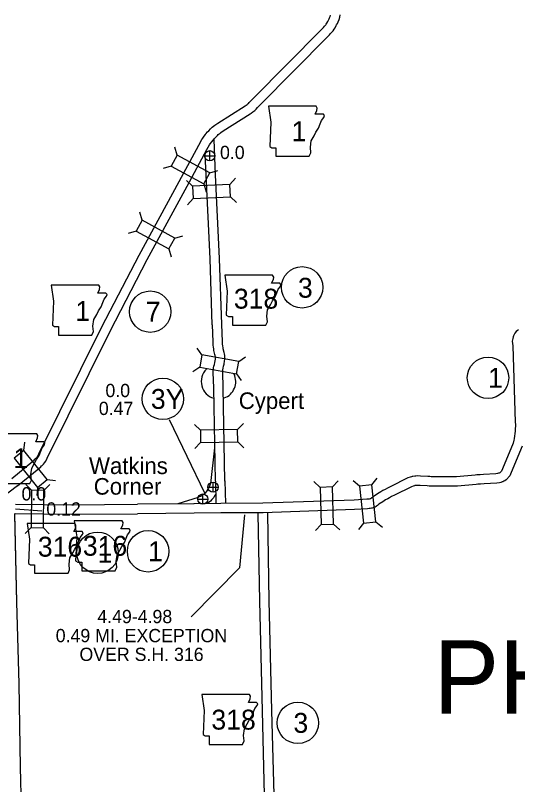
# Model space of a CAD drawing. Extents: x -939622 to -934222, y 1383701 to 1385301.
# Drawn here: x -935874.6 to -935826.6, y 1383989.8 to 1384063.3 of the extents above; entities that cross this region are included whole.
import ezdxf

# ---------------------------------------------------------------- set-up
doc = ezdxf.new("R2010")
doc.units = 0
for name, color, linetype in [('Default', 7, 'Continuous'), ('Level 10', 7, 'Continuous'), ('Level 2', 7, 'Continuous'), ('Level 20', 7, 'Continuous'), ('Level 21', 7, 'Continuous'), ('Level 24', 7, 'Continuous'), ('Level 25', 7, 'Continuous'), ('Level 26', 7, 'Continuous'), ('Level 27', 7, 'Continuous')]:
    doc.layers.add(name, color=color, linetype=linetype)

msp = doc.modelspace()

# ---------------------------------------------------------------- linework, layer by layer
at = {"layer": 'Level 10'}
for points in [[(-935856.422, 1384051.991), (-935856.278, 1384052.175), (-935856.151, 1384052.289), (-935855.982, 1384052.472), (-935855.832, 1384052.628), (-935855.694, 1384052.726), (-935855.568, 1384052.827), (-935855.48, 1384052.876), (-935855.279, 1384053.028), (-935852.676, 1384054.679), (-935852.582, 1384054.738), (-935852.473, 1384054.816), (-935852.405, 1384054.867), (-935852.357, 1384054.907), (-935852.282, 1384054.981), (-935852.149, 1384055.124), (-935851.897, 1384055.38), (-935845.4, 1384061.952), (-935845.239, 1384062.101), (-935845.179, 1384062.169), (-935845.086, 1384062.275), (-935845.015, 1384062.359), (-935844.956, 1384062.419), (-935844.918, 1384062.475), (-935844.865, 1384062.562), (-935844.775, 1384062.745), (-935844.715, 1384062.86), (-935844.644, 1384062.984), (-935844.597, 1384063.07), (-935844.553, 1384063.197), (-935844.512, 1384063.327)], [(-935855.713, 1384051.437), (-935855.618, 1384051.559), (-935855.519, 1384051.648), (-935855.328, 1384051.854), (-935855.242, 1384051.943), (-935855.153, 1384052.006), (-935855.064, 1384052.077), (-935854.988, 1384052.12), (-935854.766, 1384052.287), (-935852.199, 1384053.916), (-935852.083, 1384053.988), (-935851.941, 1384054.09), (-935851.847, 1384054.16), (-935851.75, 1384054.241), (-935851.635, 1384054.355), (-935851.499, 1384054.502), (-935851.256, 1384054.749), (-935844.773, 1384061.305), (-935844.594, 1384061.473), (-935844.505, 1384061.574), (-935844.404, 1384061.687), (-935844.349, 1384061.753), (-935844.259, 1384061.844), (-935844.162, 1384061.987), (-935844.075, 1384062.129), (-935843.971, 1384062.34), (-935843.926, 1384062.428), (-935843.858, 1384062.545), (-935843.771, 1384062.706), (-935843.698, 1384062.915), (-935843.628, 1384063.14), (-935843.603, 1384063.357)], [(-935866.365, 1384033.548), (-935862.82, 1384040.409), (-935858.995, 1384047.442), (-935857.116, 1384050.921), (-935856.822, 1384051.463), (-935856.709, 1384051.599), (-935856.582, 1384051.767), (-935856.464, 1384051.937), (-935856.422, 1384051.991)], [(-935865.565, 1384033.135), (-935862.025, 1384039.988), (-935858.204, 1384047.013), (-935856.324, 1384050.493), (-935856.073, 1384050.956), (-935856.004, 1384051.039), (-935855.852, 1384051.239), (-935855.739, 1384051.404), (-935855.713, 1384051.437)], [(-935854.911, 1384033.791), (-935855.127, 1384040.095), (-935855.513, 1384048.097), (-935855.643, 1384051.458)], [(-935855.811, 1384033.76), (-935856.027, 1384040.058), (-935856.412, 1384048.058), (-935856.489, 1384050.045)], [(-935874.994, 1384019.077), (-935872.977, 1384020.714), (-935872.851, 1384020.82), (-935872.77, 1384020.913), (-935872.678, 1384020.993), (-935872.621, 1384021.045), (-935872.577, 1384021.102), (-935872.497, 1384021.21), (-935872.386, 1384021.42), (-935866.368, 1384033.542)], [(-935874.427, 1384018.378), (-935872.402, 1384020.021), (-935872.219, 1384020.177), (-935872.135, 1384020.273), (-935872.078, 1384020.321), (-935871.956, 1384020.434), (-935871.86, 1384020.558), (-935871.733, 1384020.73), (-935871.585, 1384021.01), (-935865.562, 1384033.141)], [(-935826.538, 1384033.284), (-935826.624, 1384033.222), (-935826.775, 1384033.104), (-935826.889, 1384032.955), (-935826.956, 1384032.823), (-935827.007, 1384032.702), (-935827.035, 1384032.588), (-935827.082, 1384032.437), (-935827.141, 1384032.202), (-935827.094, 1384031.727), (-935826.855, 1384024.434), (-935826.83, 1384024.216), (-935826.835, 1384024.09), (-935826.853, 1384023.798), (-935826.851, 1384023.623), (-935826.886, 1384023.324), (-935826.908, 1384023.154), (-935826.965, 1384022.856), (-935826.991, 1384022.717), (-935827.058, 1384022.43), (-935828.08, 1384019.982), (-935828.173, 1384019.764), (-935828.174, 1384019.763), (-935828.191, 1384019.742), (-935828.228, 1384019.703), (-935828.273, 1384019.655), (-935828.299, 1384019.628), (-935828.305, 1384019.624), (-935828.321, 1384019.616), (-935828.388, 1384019.588), (-935828.413, 1384019.577), (-935828.461, 1384019.561), (-935828.538, 1384019.543), (-935828.718, 1384019.509), (-935829.877, 1384019.451), (-935830.218, 1384019.426), (-935830.394, 1384019.415), (-935830.508, 1384019.41), (-935830.689, 1384019.389), (-935832.454, 1384019.236), (-935832.554, 1384019.225), (-935832.688, 1384019.223), (-935832.814, 1384019.224), (-935833.535, 1384019.225), (-935833.913, 1384019.224), (-935834.144, 1384019.23), (-935834.491, 1384019.223), (-935834.888, 1384019.236), (-935835.031, 1384019.24), (-935835.204, 1384019.249), (-935835.898, 1384019.299), (-935836.154, 1384019.306), (-935836.344, 1384019.303), (-935836.466, 1384019.298), (-935836.629, 1384019.271), (-935836.71, 1384019.249), (-935836.768, 1384019.23), (-935836.9, 1384019.189), (-935837.115, 1384019.115), (-935838.805, 1384018.275), (-935839.075, 1384018.137), (-935839.301, 1384018.027), (-935839.502, 1384017.91), (-935839.712, 1384017.784), (-935840.011, 1384017.601), (-935840.421, 1384017.327), (-935840.584, 1384017.2), (-935840.679, 1384017.122), (-935840.689, 1384017.119), (-935840.718, 1384017.116), (-935840.823, 1384017.1), (-935840.923, 1384017.091), (-935841.039, 1384017.078), (-935842.266, 1384016.998), (-935850.983, 1384016.698), (-935855.007, 1384016.669), (-935857.564, 1384016.639)], [(-935855.515, 1384018.81), (-935855.659, 1384027.735), (-935855.719, 1384029.18), (-935855.718, 1384029.38), (-935855.71, 1384029.517), (-935855.683, 1384029.635), (-935855.652, 1384029.793), (-935855.61, 1384029.973), (-935855.579, 1384030.148), (-935855.523, 1384030.456), (-935855.513, 1384030.525), (-935855.509, 1384030.572), (-935855.513, 1384030.617), (-935855.52, 1384030.677), (-935855.544, 1384030.81), (-935855.563, 1384030.914), (-935855.661, 1384031.302), (-935855.669, 1384031.425), (-935855.703, 1384031.638), (-935855.719, 1384031.763), (-935855.731, 1384031.949), (-935855.739, 1384032.113), (-935855.81, 1384033.756)], [(-935854.615, 1384018.825), (-935854.76, 1384027.761), (-935854.819, 1384029.197), (-935854.818, 1384029.352), (-935854.816, 1384029.39), (-935854.803, 1384029.447), (-935854.772, 1384029.603), (-935854.729, 1384029.791), (-935854.693, 1384029.989), (-935854.636, 1384030.308), (-935854.618, 1384030.421), (-935854.606, 1384030.572), (-935854.617, 1384030.707), (-935854.63, 1384030.81), (-935854.658, 1384030.971), (-935854.683, 1384031.107), (-935854.769, 1384031.445), (-935854.774, 1384031.527), (-935854.812, 1384031.764), (-935854.823, 1384031.849), (-935854.833, 1384032), (-935854.84, 1384032.155), (-935854.911, 1384033.795)], [(-935826.198, 1384022.153), (-935827.251, 1384019.632), (-935827.38, 1384019.329), (-935827.45, 1384019.227), (-935827.516, 1384019.145), (-935827.573, 1384019.086), (-935827.618, 1384019.037), (-935827.71, 1384018.943), (-935827.841, 1384018.849), (-935827.95, 1384018.795), (-935828.033, 1384018.761), (-935828.091, 1384018.735), (-935828.216, 1384018.694), (-935828.349, 1384018.662), (-935828.612, 1384018.613), (-935829.822, 1384018.553), (-935830.158, 1384018.528), (-935830.348, 1384018.516), (-935830.437, 1384018.513), (-935830.598, 1384018.494), (-935832.364, 1384018.34), (-935832.497, 1384018.325), (-935832.688, 1384018.323), (-935832.82, 1384018.324), (-935833.533, 1384018.325), (-935833.923, 1384018.324), (-935834.148, 1384018.33), (-935834.497, 1384018.323), (-935834.916, 1384018.336), (-935835.068, 1384018.341), (-935835.261, 1384018.351), (-935835.942, 1384018.4), (-935836.16, 1384018.406), (-935836.318, 1384018.404), (-935836.371, 1384018.401), (-935836.441, 1384018.39), (-935836.456, 1384018.386), (-935836.493, 1384018.373), (-935836.618, 1384018.334), (-935836.768, 1384018.283), (-935838.4, 1384017.471), (-935838.673, 1384017.332), (-935838.876, 1384017.233), (-935839.045, 1384017.135), (-935839.245, 1384017.015), (-935839.525, 1384016.843), (-935839.894, 1384016.596), (-935840.022, 1384016.497), (-935840.11, 1384016.425), (-935840.139, 1384016.401), (-935840.233, 1384016.316), (-935840.533, 1384016.232), (-935840.598, 1384016.224), (-935840.715, 1384016.206), (-935840.831, 1384016.195), (-935840.96, 1384016.181), (-935842.221, 1384016.099), (-935850.965, 1384015.798), (-935854.999, 1384015.769), (-935857.554, 1384015.739)], [(-935855.599, 1384021.999), (-935855.997, 1384018.598), (-935856.007, 1384018.509), (-935856.012, 1384018.49), (-935856.05, 1384018.413), (-935856.138, 1384018.22), (-935856.179, 1384018.146), (-935856.247, 1384018.031), (-935856.343, 1384017.883), (-935856.411, 1384017.778), (-935856.437, 1384017.746), (-935856.504, 1384017.673), (-935856.603, 1384017.574), (-935856.664, 1384017.522), (-935856.735, 1384017.47), (-935856.819, 1384017.424), (-935856.942, 1384017.357), (-935857.058, 1384017.299), (-935857.126, 1384017.269), (-935857.176, 1384017.253), (-935859.104, 1384016.645)], [(-935855.515, 1384018.807), (-935855.464, 1384016.672)], [(-935854.615, 1384018.828), (-935854.564, 1384016.672)], [(-935874.443, 1384018.366), (-935876.198, 1384017.071), (-935878.006, 1384015.744), (-935878.186, 1384015.587)], [(-935855.505, 1384017.521), (-935855.587, 1384017.394), (-935855.682, 1384017.249), (-935855.756, 1384017.157), (-935855.853, 1384017.051), (-935855.993, 1384016.911), (-935856.108, 1384016.813), (-935856.251, 1384016.709), (-935856.34, 1384016.661)], [(-935874.639, 1384016.626), (-935869.261, 1384016.558), (-935862.965, 1384016.596)], [(-935857.562, 1384016.639), (-935862.966, 1384016.596)], [(-935874.651, 1384015.727), (-935869.264, 1384015.658), (-935862.959, 1384015.696)], [(-935857.555, 1384015.739), (-935862.959, 1384015.696)], [(-935850.814, 1383988.81), (-935851.014, 1383996.866), (-935851.268, 1384007.347), (-935851.415, 1384015.729)], [(-935849.914, 1383988.822), (-935850.114, 1383996.888), (-935850.368, 1384007.366), (-935850.515, 1384015.757)]]:
    msp.add_lwpolyline(points, dxfattribs=at)
at = {"layer": 'Level 2'}
for points in [[(-935874.733, 1384015.72), (-935874.523, 1384007.256), (-935874.318, 1383999.431), (-935874.179, 1383991.495), (-935873.992, 1383983.582), (-935873.79, 1383975.609), (-935873.634, 1383967.743), (-935873.76, 1383967.737), (-935873.69, 1383964.539)], [(-935874.73, 1384015.616), (-935874.523, 1384007.256), (-935874.318, 1383999.431), (-935874.179, 1383991.495), (-935873.992, 1383983.582), (-935873.79, 1383975.609), (-935873.634, 1383967.743), (-935873.76, 1383967.737), (-935873.69, 1383964.539)]]:
    msp.add_lwpolyline(points, dxfattribs=at)
at = {"layer": 'Level 20'}
for p, q in [((-935859.185, 1384049.951), (-935859.411, 1384050.71)), ((-935859.749, 1384048.906), (-935860.508, 1384048.68)), ((-935856.049, 1384048.257), (-935855.29, 1384048.484)), ((-935857.694, 1384047.002), (-935858.279, 1384047.535)), ((-935856.614, 1384047.212), (-935856.387, 1384046.453)), ((-935854.133, 1384047.166), (-935853.6, 1384047.752)), ((-935857.639, 1384045.815), (-935858.172, 1384045.23)), ((-935854.079, 1384045.98), (-935853.493, 1384045.446)), ((-935862.517, 1384043.752), (-935862.739, 1384044.512)), ((-935863.086, 1384042.71), (-935863.846, 1384042.487)), ((-935859.389, 1384042.043), (-935858.629, 1384042.266)), ((-935859.959, 1384041.001), (-935859.736, 1384040.241)), ((-935856.8, 1384030.883), (-935857.251, 1384031.534)), ((-935853.292, 1384030.25), (-935852.642, 1384030.702)), ((-935857.011, 1384029.714), (-935857.661, 1384029.262)), ((-935853.503, 1384029.081), (-935853.051, 1384028.431)), ((-935853.39, 1384023.747), (-935852.839, 1384024.316)), ((-935856.953, 1384023.69), (-935857.523, 1384024.24)), ((-935853.39, 1384023.747), (-935856.953, 1384023.69)), ((-935856.953, 1384023.69), (-935856.934, 1384022.502)), ((-935853.371, 1384022.559), (-935853.39, 1384023.747)), ((-935873.826, 1384021.738), (-935873.743, 1384022.526)), ((-935856.934, 1384022.502), (-935857.485, 1384021.933)), ((-935856.934, 1384022.502), (-935853.371, 1384022.559)), ((-935853.371, 1384022.559), (-935852.802, 1384022.009)), ((-935873.092, 1384017.939), (-935873.645, 1384018.506)), ((-935871.904, 1384017.924), (-935871.337, 1384018.477)), ((-935871.586, 1384018.966), (-935870.799, 1384018.883)), ((-935845.516, 1384018.22), (-935846.094, 1384018.762)), ((-935844.329, 1384018.259), (-935843.787, 1384018.837)), ((-935841.732, 1384018.343), (-935842.349, 1384018.84)), ((-935840.551, 1384018.47), (-935840.054, 1384019.087)), ((-935872.51, 1384018.22), (-935872.594, 1384017.432)), ((-935841.351, 1384014.8), (-935841.848, 1384014.183)), ((-935840.17, 1384014.927), (-935839.553, 1384014.43)), ((-935873.137, 1384014.375), (-935873.704, 1384013.822)), ((-935871.949, 1384014.36), (-935871.396, 1384013.793)), ((-935845.4, 1384014.658), (-935845.942, 1384014.08)), ((-935844.213, 1384014.697), (-935843.635, 1384014.155))]:
    msp.add_line(p, q, dxfattribs=at)
for points in [[(-935859.749, 1384048.906), (-935856.614, 1384047.212), (-935856.049, 1384048.257), (-935859.185, 1384049.951)], [(-935857.639, 1384045.815), (-935854.079, 1384045.98), (-935854.133, 1384047.166), (-935857.694, 1384047.002)], [(-935859.389, 1384042.043), (-935862.517, 1384043.752), (-935863.086, 1384042.71), (-935859.959, 1384041.001)], [(-935857.011, 1384029.714), (-935853.503, 1384029.081), (-935853.292, 1384030.25), (-935856.8, 1384030.883)], [(-935874.75, 1384020.992), (-935872.51, 1384018.22), (-935871.586, 1384018.966), (-935873.826, 1384021.738)], [(-935840.17, 1384014.927), (-935840.551, 1384018.47), (-935841.732, 1384018.343), (-935841.351, 1384014.8)], [(-935871.949, 1384014.36), (-935871.904, 1384017.924), (-935873.092, 1384017.939), (-935873.137, 1384014.375)], [(-935845.516, 1384018.22), (-935845.4, 1384014.658), (-935844.213, 1384014.697), (-935844.329, 1384018.259)]]:
    msp.add_lwpolyline(points, close=True, dxfattribs=at)
at = {"layer": 'Level 21'}
for points in [[(-935850.449, 1384054.63), (-935850.22, 1384053.107), (-935850.322, 1384050.798), (-935850.119, 1384050.671), (-935849.738, 1384050.671), (-935849.738, 1384049.859), (-935846.541, 1384049.859), (-935846.388, 1384050.189), (-935846.439, 1384050.722), (-935846.363, 1384051.331), (-935846.084, 1384051.813), (-935845.906, 1384052.168), (-935845.652, 1384052.549), (-935845.5, 1384052.955), (-935845.373, 1384053.285), (-935845.145, 1384053.564), (-935845.094, 1384053.741), (-935845.196, 1384053.868), (-935845.982, 1384053.868), (-935845.805, 1384054.224), (-935845.779, 1384054.452), (-935845.885, 1384054.627)], [(-935854.606, 1384038.491), (-935854.377, 1384036.968), (-935854.479, 1384034.659), (-935854.276, 1384034.532), (-935853.895, 1384034.532), (-935853.895, 1384033.72), (-935850.698, 1384033.72), (-935850.546, 1384034.05), (-935850.596, 1384034.583), (-935850.52, 1384035.192), (-935850.241, 1384035.674), (-935850.063, 1384036.029), (-935849.81, 1384036.41), (-935849.657, 1384036.816), (-935849.53, 1384037.146), (-935849.302, 1384037.425), (-935849.251, 1384037.603), (-935849.353, 1384037.73), (-935850.14, 1384037.73), (-935849.962, 1384038.085), (-935849.937, 1384038.313), (-935850.042, 1384038.489)], [(-935871.231, 1384037.542), (-935871.002, 1384036.019), (-935871.104, 1384033.71), (-935870.901, 1384033.583), (-935870.52, 1384033.583), (-935870.52, 1384032.771), (-935867.323, 1384032.771), (-935867.17, 1384033.101), (-935867.221, 1384033.634), (-935867.145, 1384034.243), (-935866.866, 1384034.725), (-935866.688, 1384035.08), (-935866.435, 1384035.461), (-935866.282, 1384035.867), (-935866.155, 1384036.197), (-935865.927, 1384036.476), (-935865.876, 1384036.654), (-935865.978, 1384036.781), (-935866.764, 1384036.781), (-935866.587, 1384037.136), (-935866.561, 1384037.364), (-935866.667, 1384037.54)], [(-935877.164, 1384023.345), (-935876.935, 1384021.823), (-935877.037, 1384019.513), (-935876.834, 1384019.386), (-935876.453, 1384019.386), (-935876.453, 1384018.574), (-935873.256, 1384018.574), (-935873.104, 1384018.904), (-935873.154, 1384019.437), (-935873.078, 1384020.046), (-935872.799, 1384020.528), (-935872.621, 1384020.884), (-935872.368, 1384021.264), (-935872.215, 1384021.67), (-935872.088, 1384022), (-935871.86, 1384022.279), (-935871.809, 1384022.457), (-935871.911, 1384022.584), (-935872.698, 1384022.584), (-935872.52, 1384022.939), (-935872.494, 1384023.168), (-935872.6, 1384023.343)], [(-935873.514, 1384014.776), (-935873.286, 1384013.254), (-935873.387, 1384010.944), (-935873.184, 1384010.818), (-935872.803, 1384010.818), (-935872.803, 1384010.006), (-935869.606, 1384010.006), (-935869.454, 1384010.335), (-935869.504, 1384010.868), (-935869.428, 1384011.477), (-935869.149, 1384011.96), (-935868.971, 1384012.315), (-935868.718, 1384012.695), (-935868.565, 1384013.102), (-935868.439, 1384013.431), (-935868.21, 1384013.711), (-935868.159, 1384013.888), (-935868.261, 1384014.015), (-935869.048, 1384014.015), (-935868.87, 1384014.37), (-935868.845, 1384014.599), (-935868.95, 1384014.774)], [(-935869.009, 1384015.026), (-935868.78, 1384013.503), (-935868.882, 1384011.194), (-935868.679, 1384011.067), (-935868.298, 1384011.067), (-935868.298, 1384010.255), (-935865.101, 1384010.255), (-935864.948, 1384010.585), (-935864.999, 1384011.118), (-935864.923, 1384011.727), (-935864.644, 1384012.209), (-935864.466, 1384012.564), (-935864.212, 1384012.945), (-935864.06, 1384013.351), (-935863.933, 1384013.681), (-935863.705, 1384013.96), (-935863.654, 1384014.138), (-935863.756, 1384014.265), (-935864.542, 1384014.265), (-935864.365, 1384014.62), (-935864.339, 1384014.848), (-935864.444, 1384015.024)], [(-935856.828, 1383998.43), (-935856.6, 1383996.908), (-935856.702, 1383994.598), (-935856.498, 1383994.471), (-935856.118, 1383994.471), (-935856.118, 1383993.659), (-935852.92, 1383993.659), (-935852.768, 1383993.989), (-935852.819, 1383994.522), (-935852.743, 1383995.131), (-935852.464, 1383995.613), (-935852.286, 1383995.969), (-935852.032, 1383996.349), (-935851.88, 1383996.755), (-935851.753, 1383997.085), (-935851.525, 1383997.364), (-935851.474, 1383997.542), (-935851.575, 1383997.669), (-935852.362, 1383997.669), (-935852.184, 1383998.024), (-935852.159, 1383998.252), (-935852.264, 1383998.428)]]:
    msp.add_lwpolyline(points, close=True, dxfattribs=at)
at = {"layer": 'Level 24'}
for start, end in [(134.19304, 254.05463), (289.50246, 25.51387)]:
    msp.add_arc((-935855.222, 1384028.317), 1.65, start, end, dxfattribs=at)
at = {"layer": 'Level 25'}
msp.add_line((-935874.637, 1384016.18), (-935872.115, 1384015.982), dxfattribs=at)
msp.add_lwpolyline([(-935852.737, 1384015.608), (-935853.199, 1384010.522), (-935857.823, 1384005.832)], dxfattribs=at)
at = {"layer": 'Level 26'}
for p, q in [((-935856.06, 1384049.419), (-935856.06, 1384050.394)), ((-935856.548, 1384049.906), (-935855.573, 1384049.906)), ((-935855.745, 1384017.755), (-935855.745, 1384018.73)), ((-935856.233, 1384018.242), (-935855.258, 1384018.242)), ((-935857.202, 1384017.1), (-935856.227, 1384017.1)), ((-935856.715, 1384016.612), (-935856.715, 1384017.587))]:
    msp.add_line(p, q, dxfattribs=at)
for centre in [(-935856.06, 1384049.906), (-935855.745, 1384018.242), (-935856.715, 1384017.1)]:
    msp.add_circle(centre, 0.487, dxfattribs=at)
at = {"layer": 'Level 27'}
msp.add_line((-935859.929, 1384024.7), (-935856.56, 1384017.698), dxfattribs=at)
for centre in [(-935847.224, 1384037.33), (-935861.75, 1384035.006), (-935829.452, 1384028.687), (-935860.539, 1384026.67), (-935861.955, 1384012.11), (-935866.78, 1384011.969), (-935847.63, 1383995.714)]:
    msp.add_circle(centre, 1.98, dxfattribs=at)

# ---------------------------------------------------------------- texts
at = {"layer": 'Default'}
msp.add_text('PHILLIPS', height=7, dxfattribs=at).set_placement((-935834.64, 1383996.605))
at = {"layer": 'Level 21'}
for s, height, p in [('1', 1.901, (-935848.236, 1384051.297)), ('318', 1.9008, (-935853.75, 1384035.297)), ('1', 1.901, (-935868.913, 1384034.121)), ('1', 1.901, (-935874.833, 1384020.057)), ('316', 1.9008, (-935872.493, 1384011.596)), ('316', 1.9008, (-935868.189, 1384011.685)), ('318', 1.9008, (-935855.9, 1383995.071))]:
    msp.add_text(s, height=height, dxfattribs=at).set_placement(p)
at = {"layer": 'Level 24'}
for s, p in [('Cypert', (-935853.281, 1384025.708)), ('Watkins', (-935867.6, 1384019.489)), ('Corner', (-935867.147, 1384017.522))]:
    msp.add_text(s, height=1.584, dxfattribs=at).set_placement(p)
at = {"layer": 'Level 25'}
for s, p in [('0.0', (-935855.077, 1384049.591)), ('0.0', (-935866.03, 1384026.84)), ('0.47', (-935866.661, 1384025.13)), ('0.0', (-935874.05, 1384016.966)), ('0.12', (-935871.679, 1384015.521)), ('4.49-4.98', (-935866.805, 1384005.241)), ('0.49 MI. EXCEPTION', (-935870.782, 1384003.421)), ('OVER S.H. 316', (-935868.511, 1384001.631))]:
    msp.add_text(s, height=1.2672, dxfattribs=at).set_placement(p)
at = {"layer": 'Level 27'}
for s, height, p in [('3', 1.901, (-935847.627, 1384036.339)), ('7', 1.901, (-935862.175, 1384034.056)), ('1', 1.901, (-935829.452, 1384027.737)), ('3Y', 1.9008, (-935861.685, 1384025.719)), ('1', 1.901, (-935866.78, 1384011.019)), ('1', 1.901, (-935861.955, 1384011.159)), ('3', 1.901, (-935848.055, 1383994.763))]:
    msp.add_text(s, height=height, dxfattribs=at).set_placement(p)

doc.saveas('drawing.dxf')
